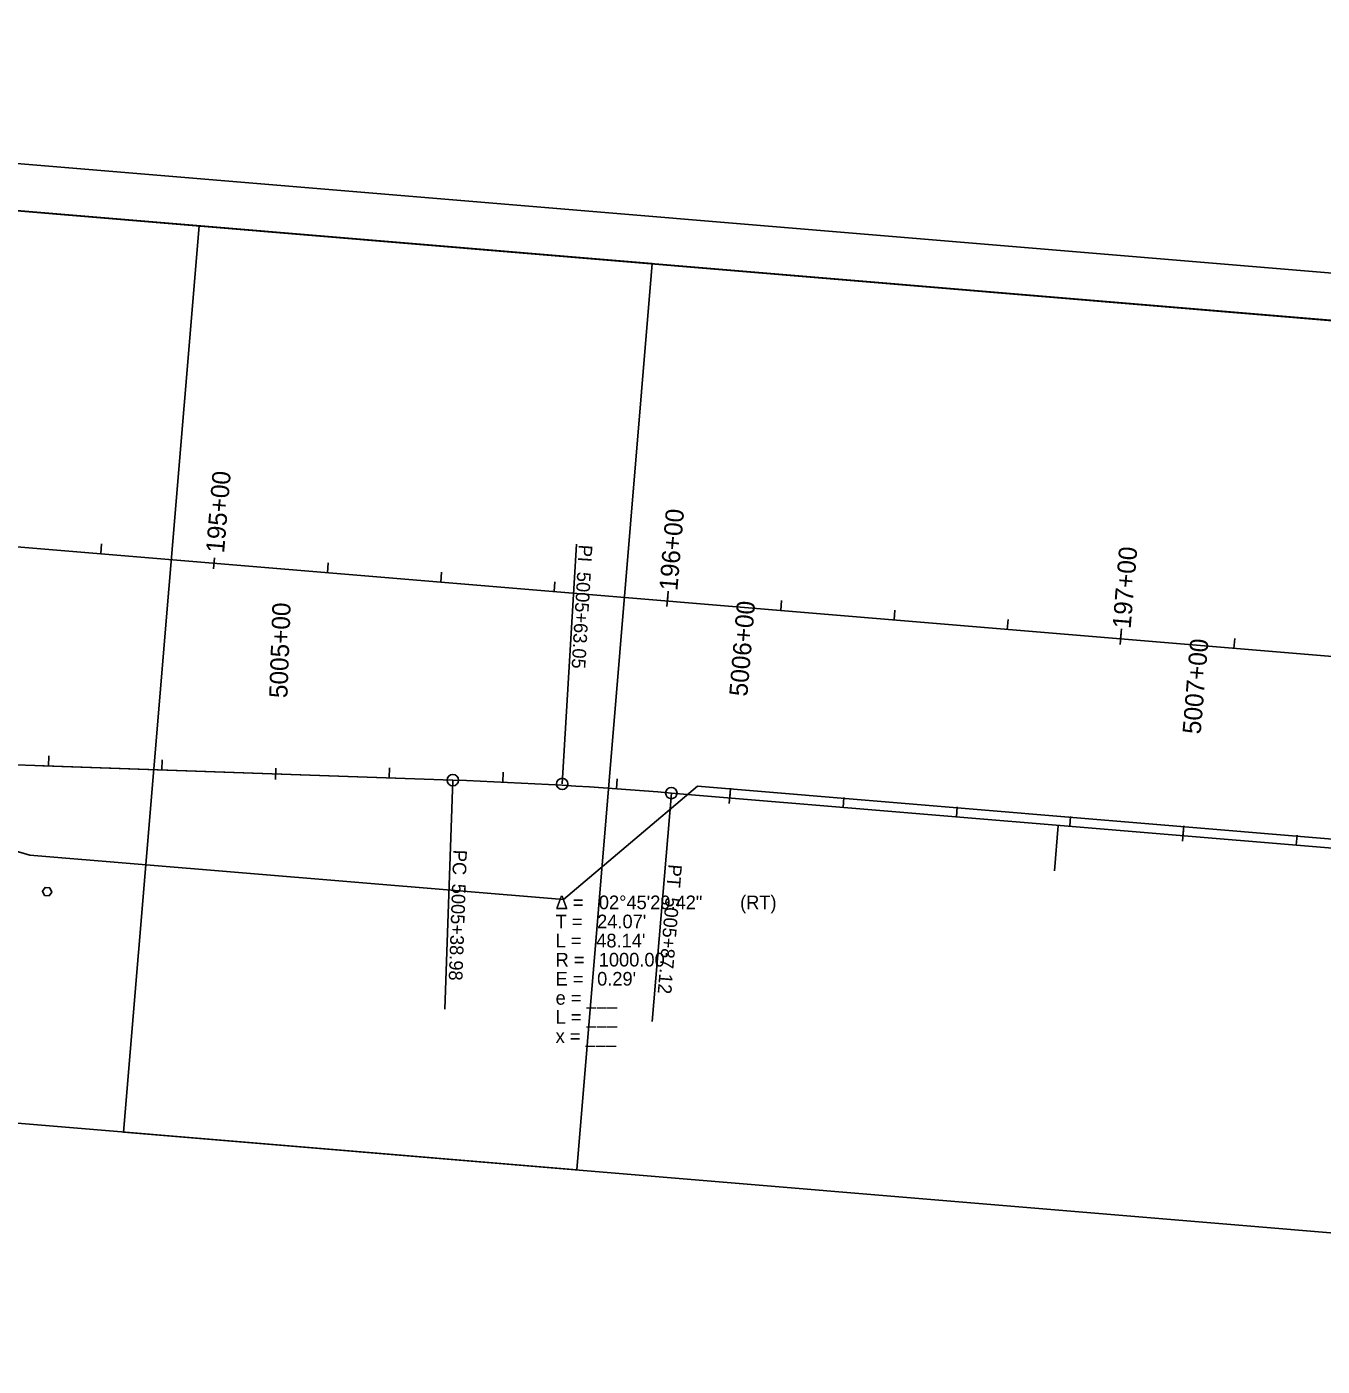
# Model space of a CAD drawing. Extents: x 20500393 to 20505339, y 7953466 to 7954298.
# Drawn here: x 20503162 to 20503446.8, y 7953593.2 to 7953887.7 of the extents above; entities that cross this region are included whole.
import ezdxf

# ---------------------------------------------------------------- set-up
doc = ezdxf.new("R2010")
doc.units = 0
for name, color, linetype in [('_CIVIL_CONSTRUCTION', 7, 'Continuous'), ('Alignment', 7, 'Continuous'), ('Draft_2', 7, 'Continuous'), ('Draft_3', 7, 'Continuous'), ('Draft_7', 7, 'Continuous'), ('NamedBoundary', 7, 'Continuous'), ('RowProposed', 7, 'Continuous'), ('TextAlignment', 7, 'Continuous'), ('TextAlignmentLrg', 7, 'Continuous'), ('TextAlignmentSml', 7, 'Continuous')]:
    doc.layers.add(name, color=color, linetype=linetype)

msp = doc.modelspace()

# ---------------------------------------------------------------- linework, layer by layer
at = {"layer": '_CIVIL_CONSTRUCTION'}
for p, q in [((20502804.53, 7953803.04), (20504247.96, 7953682.58)), ((20502804.53, 7953803.04), (20504247.96, 7953682.58)), ((20503075.29, 7953728.42), (20503255.62, 7953722.08)), ((20503303.67, 7953719.24), (20504244.47, 7953640.72))]:
    msp.add_line(p, q, dxfattribs=at)
msp.add_arc((20503220.51, 7952722.7), 1000, 85.22957, 87.98774, dxfattribs=at)
at = {"layer": 'Alignment'}
for p, q in [((20503075.29, 7953728.42), (20503255.62, 7953722.08)), ((20503075.29, 7953728.42), (20503255.62, 7953722.08)), ((20503303.67, 7953719.24), (20504244.47, 7953640.72)), ((20503303.67, 7953719.24), (20504244.47, 7953640.72)), ((20503388.73, 7953712.14), (20503387.89, 7953702.17))]:
    msp.add_line(p, q, dxfattribs=at)
msp.add_arc((20503220.51, 7952722.7), 1000, 85.22957, 87.98774, dxfattribs=at)
msp.add_arc((20503220.51, 7952722.7), 1000, 85.22957, 87.98774, dxfattribs=at)
at = {"layer": 'Draft_2'}
for p, q in [((20502811.52, 7953886.75), (20504254.94, 7953766.29)), ((20502810.65, 7953876.37), (20504254.08, 7953755.91))]:
    msp.add_line(p, q, dxfattribs=at)
at = {"layer": 'Draft_3'}
for p, q in [((20503165.46, 7953725.25), (20503255.62, 7953722.08)), ((20503303.67, 7953719.24), (20504244.47, 7953640.72)), ((20503303.67, 7953719.24), (20504244.47, 7953640.72))]:
    msp.add_line(p, q, dxfattribs=at)
msp.add_arc((20503220.51, 7952722.7), 1000, 85.22957, 87.98774, dxfattribs=at)
at = {"layer": 'Draft_7'}
for p, q in [((20503090.75, 7953726.26), (20503162.66, 7953705.61)), ((20503279.96, 7953695.82), (20503309.44, 7953720.76)), ((20503309.44, 7953720.76), (20503652.67, 7953692.12)), ((20503162.66, 7953705.61), (20503279.96, 7953695.82))]:
    msp.add_line(p, q, dxfattribs=at)
at = {"layer": 'NamedBoundary'}
for points in [[(20502675.82, 7953887.73), (20502659.18, 7953688.42), (20503282.86, 7953636.38), (20503299.49, 7953835.68)], [(20503199.83, 7953844), (20503183.2, 7953644.69), (20503800.15, 7953593.21), (20503816.78, 7953792.52)]]:
    msp.add_lwpolyline(points, close=True, dxfattribs=at)
at = {"layer": 'RowProposed'}
msp.add_lwpolyline([(20503165.84, 7953696.73), (20503166.86, 7953696.65), (20503167.44, 7953697.48), (20503167, 7953698.4), (20503165.99, 7953698.49), (20503165.41, 7953697.65)], close=True, dxfattribs=at)
at = {"layer": 'TextAlignment'}
for p, q in [((20503279.68, 7953721.24), (20503282.8, 7953773.95)), ((20503282.8, 7953773.95), (20503282.8, 7953773.95)), ((20503255.62, 7953722.08), (20503253.85, 7953671.72)), ((20503303.67, 7953719.24), (20503299.48, 7953669.01)), ((20503253.85, 7953671.72), (20503253.85, 7953671.72)), ((20503299.48, 7953669.01), (20503299.48, 7953669.01))]:
    msp.add_line(p, q, dxfattribs=at)
for centre in [(20503255.62, 7953722.08), (20503279.68, 7953721.24), (20503303.67, 7953719.24)]:
    msp.add_circle(centre, 1.25, dxfattribs=at)
at = {"layer": 'TextAlignmentLrg'}
for p, q in [((20503203.25, 7953770.99), (20503203.04, 7953768.55)), ((20503302.8, 7953761.46), (20503302.98, 7953763.63)), ((20503402.45, 7953753.14), (20503402.63, 7953755.32)), ((20503216.71, 7953724.68), (20503216.62, 7953722.23)), ((20503316.51, 7953718.17), (20503316.69, 7953720.34)), ((20503416.16, 7953709.85), (20503416.34, 7953712.03))]:
    msp.add_line(p, q, dxfattribs=at)
at = {"layer": 'TextAlignmentSml'}
for p, q in [((20503178.23, 7953771.85), (20503178.41, 7953774.03)), ((20503203.25, 7953770.99), (20503203.04, 7953768.55)), ((20503228.06, 7953767.69), (20503228.24, 7953769.87)), ((20503252.97, 7953765.61), (20503253.15, 7953767.79)), ((20503277.89, 7953763.53), (20503278.07, 7953765.71)), ((20503302.9, 7953762.68), (20503302.7, 7953760.24)), ((20503327.71, 7953759.38), (20503327.89, 7953761.55)), ((20503352.63, 7953757.3), (20503352.81, 7953759.47)), ((20503377.54, 7953755.22), (20503377.72, 7953757.39)), ((20503402.55, 7953754.36), (20503402.35, 7953751.92)), ((20503427.37, 7953751.06), (20503427.55, 7953753.24)), ((20503166.7, 7953725.21), (20503166.77, 7953727.39)), ((20503191.68, 7953724.33), (20503191.76, 7953726.51)), ((20503216.71, 7953724.68), (20503216.62, 7953722.23)), ((20503241.65, 7953722.57), (20503241.73, 7953724.76)), ((20503266.63, 7953721.64), (20503266.73, 7953723.82)), ((20503291.59, 7953720.17), (20503291.74, 7953722.35)), ((20503316.61, 7953719.39), (20503316.41, 7953716.95)), ((20503341.42, 7953716.09), (20503341.6, 7953718.26)), ((20503366.33, 7953714.01), (20503366.52, 7953716.18)), ((20503391.25, 7953711.93), (20503391.43, 7953714.1)), ((20503416.26, 7953711.07), (20503416.06, 7953708.63)), ((20503441.07, 7953707.77), (20503441.26, 7953709.95))]:
    msp.add_line(p, q, dxfattribs=at)

# ---------------------------------------------------------------- texts
at = {"layer": 'TextAlignment'}
for s, rotation, p in [('PI ', 266.6087, (20503283.34, 7953773.91)), ('5005+63.05', 266.6087, (20503282.99, 7953767.95)), ('PC', 267.9877, (20503255.74, 7953706.81)), ('PT', 265.2296, (20503303.03, 7953703.66)), ('5005+38.98', 267.9877, (20503255.48, 7953699.34)), ('5005+87.12', 265.2296, (20503302.43, 7953696.43))]:
    msp.add_text(s, height=3, rotation=rotation, dxfattribs=at).set_placement(p)
for s, p in [('Δ = ', (20503278.23, 7953693.7)), ('02°45\'29.42"', (20503287.73, 7953693.7)), (' (RT)', (20503317.67, 7953693.7)), ('T = ', (20503278.23, 7953689.5)), ("24.07'", (20503287.35, 7953689.5)), ('L = ', (20503278.23, 7953685.3)), ("48.14'", (20503287.16, 7953685.3)), ('R = ', (20503278.23, 7953681.1)), ("1000.00'", (20503287.71, 7953681.1)), ('E = ', (20503278.23, 7953676.9)), ("0.29'", (20503287.35, 7953676.9)), ('e = ___ ', (20503278.23, 7953672.7)), ('L = ___', (20503278.23, 7953668.5)), ('x = ___', (20503278.23, 7953664.3))]:
    msp.add_text(s, height=3, dxfattribs=at).set_placement(p)
at = {"layer": 'TextAlignmentSml'}
for s, rotation, p in [('195+00', 85.2296, (20503205.33, 7953771.91)), ('196+00', 85.2296, (20503304.99, 7953763.6)), ('197+00', 85.2296, (20503404.64, 7953755.28)), ('5005+00', 87.9877, (20503219.25, 7953740.06)), ('5006+00', 85.2296, (20503320.37, 7953740.38)), ('5007+00', 85.2296, (20503420.03, 7953732.07))]:
    msp.add_text(s, height=4.008, rotation=rotation, dxfattribs=at).set_placement(p)

doc.saveas('drawing.dxf')
